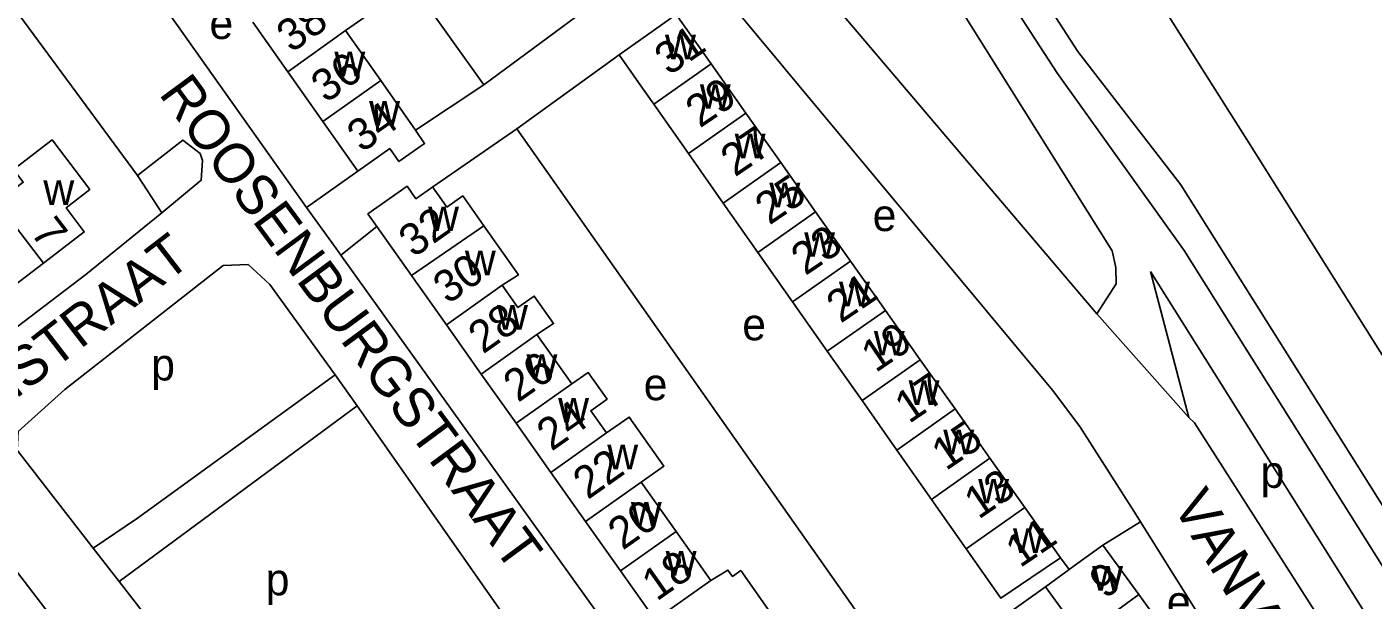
# Model space of a CAD drawing. Extents: x 158848 to 160613, y 385889 to 387762.
# Drawn here: x 160280.6 to 160449.1, y 386672.8 to 386744.6 of the extents above; entities that cross this region are included whole.
import ezdxf

# ---------------------------------------------------------------- set-up
doc = ezdxf.new("R2010")
doc.units = 0
for name, color, linetype in [('BLT_Basislijn', 7, 'Continuous'), ('BLT_Bebouwing', 7, 'Continuous'), ('BLT_Centroide', 7, 'Continuous'), ('BLT_Huisnummer', 7, 'Continuous'), ('BLT_Huisnummer_ tussenligend', 7, 'Continuous'), ('BLT_Onderverdeling_panden', 7, 'Continuous'), ('BLT_Straatnaam', 7, 'Continuous')]:
    doc.layers.add(name, color=color, linetype=linetype)

msp = doc.modelspace()

# ---------------------------------------------------------------- linework, layer by layer
at = {"layer": 'BLT_Basislijn'}
for p, q in [((160373.41, 386825.27), (160433.49, 386730.11)), ((160315.59, 386721.93), (160287.01, 386762.27)), ((160271.82, 386756.68), (160294.41, 386725.95)), ((160337.79, 386737.32), (160349.27, 386745.78)), ((160341.91, 386731.79), (160354.7, 386741.07)), ((160337.79, 386737.32), (160329.23, 386731.61)), ((160341.91, 386731.79), (160331.38, 386724.52)), ((160390.87, 386662.24), (160341.91, 386731.79)), ((160433.49, 386730.11), (160491.73, 386637.45)), ((160297.47, 386721.3), (160294.41, 386725.95)), ((160315.59, 386721.93), (160322.01, 386726.51)), ((160425.02, 386724.79), (160483.26, 386632.13)), ((160324.38, 386719.57), (160319.86, 386716)), ((160426.05, 386695.68), (160414.52, 386708.62)), ((160321.92, 386697.11), (160319.16, 386701)), ((160321.92, 386697.11), (160292.15, 386675.12)), ((160321.92, 386697.11), (160343.06, 386667)), ((160415.28, 386679.69), (160419.96, 386682.62)), ((160419.96, 386682.62), (160433.5, 386661.1)), ((160288.87, 386679.32), (160292.15, 386675.12)), ((160411.06, 386676.64), (160409.96, 386678.1)), ((160314.74, 386645.95), (160292.15, 386675.12)), ((160408.09, 386674.48), (160392.26, 386663.22))]:
    msp.add_line(p, q, dxfattribs=at)
for points in [[(160357.58, 386818.68), (160409.58, 386738.73), (160425.46, 386716.58)], [(160332.3, 386805.38), (160341.21, 386811.28), (160354.98, 386814.58), (160416.45, 386716.52), (160416.9, 386714.44), (160416.93, 386712.38), (160414.52, 386708.62)], [(160332.3, 386805.38), (160414.52, 386708.62)], [(160337.79, 386737.32), (160316.29, 386767.38), (160311.2, 386774.46), (160308.81, 386777.78)], [(160401.65, 386757.71), (160412.15, 386741.49), (160425.02, 386724.79)], [(160419.96, 386682.62), (160419.42, 386683.49), (160412.39, 386694.53), (160408.97, 386699.1), (160367.01, 386749.49)], [(160294.41, 386725.95), (160300.1, 386730.39), (160302.27, 386728.69), (160302.58, 386727.84), (160302.39, 386725.36), (160297.47, 386721.3)], [(160319.86, 386716), (160319.29, 386716.8), (160315.79, 386721.65), (160315.59, 386721.93)], [(160297.47, 386721.3), (160287.96, 386713.58), (160256.88, 386689.9)], [(160425.46, 386716.58), (160511.71, 386579.35), (160518.16, 386566.97)], [(160319.16, 386701), (160310.98, 386712.3), (160308.27, 386714.83), (160305.15, 386714.7), (160285.31, 386699.15), (160279.48, 386693.93), (160279.36, 386691.57), (160288.87, 386679.32)], [(160351.52, 386600.17), (160336.02, 386620.68), (160362.23, 386641.04), (160363.62, 386643.32), (160365.03, 386646.71), (160365.03, 386651.18), (160364.3, 386653.42), (160362.43, 386656.6), (160319.86, 386716)], [(160426.05, 386695.68), (160421.22, 386713.92)], [(160421.22, 386713.92), (160466.78, 386641.44), (160462.63, 386638.83)], [(160319.16, 386701), (160294.41, 386683.05), (160288.87, 386679.32)], [(160462.63, 386638.83), (160426.74, 386694.99), (160426.05, 386695.68)], [(160250.58, 386672.17), (160268.02, 386685.39), (160268.98, 386685.74), (160271.92, 386685.34), (160273.79, 386683.57), (160325.19, 386616.52), (160325.69, 386615.85)]]:
    msp.add_lwpolyline(points, dxfattribs=at)
at = {"layer": 'BLT_Bebouwing'}
for p, q in [((160308.86, 386745.14), (160313.25, 386738.93)), ((160361.86, 386746.09), (160354.7, 386741.07)), ((160366.22, 386739.92), (160361.86, 386746.09)), ((160324.89, 386737.85), (160320.48, 386744.1)), ((160313.25, 386738.93), (160317.63, 386732.72)), ((160370.58, 386733.75), (160366.22, 386739.92)), ((160329.23, 386731.61), (160324.89, 386737.85)), ((160359.05, 386734.88), (160363.39, 386728.7)), ((160374.95, 386727.58), (160370.58, 386733.75)), ((160317.63, 386732.72), (160322.01, 386726.51)), ((160363.39, 386728.7), (160367.74, 386722.51)), ((160379.31, 386721.41), (160374.95, 386727.58)), ((160367.74, 386722.51), (160372.08, 386716.33)), ((160383.68, 386715.24), (160379.31, 386721.41)), ((160324.38, 386719.57), (160328.74, 386713.42)), ((160372.08, 386716.33), (160376.43, 386710.15)), ((160388.04, 386709.07), (160383.68, 386715.24)), ((160328.74, 386713.42), (160333.09, 386707.26)), ((160376.43, 386710.15), (160380.77, 386703.96)), ((160392.41, 386702.9), (160388.04, 386709.07)), ((160333.09, 386707.26), (160337.45, 386701.1)), ((160348.79, 386699.89), (160344.43, 386706.05)), ((160380.77, 386703.96), (160385.12, 386697.78)), ((160396.77, 386696.73), (160392.41, 386702.9)), ((160337.45, 386701.1), (160341.81, 386694.95)), ((160385.12, 386697.78), (160389.46, 386691.59)), ((160401.14, 386690.56), (160396.77, 386696.73)), ((160341.81, 386694.95), (160346.17, 386688.79)), ((160389.46, 386691.59), (160393.81, 386685.41)), ((160405.51, 386684.39), (160401.14, 386690.56)), ((160346.17, 386688.79), (160350.52, 386682.64)), ((160361.85, 386681.41), (160357.49, 386687.57)), ((160393.81, 386685.41), (160398.15, 386679.23)), ((160409.96, 386678.1), (160405.51, 386684.39)), ((160350.52, 386682.64), (160354.88, 386676.48)), ((160366.2, 386675.25), (160361.85, 386681.41)), ((160419.77, 386673.5), (160415.28, 386679.69)), ((160354.88, 386676.48), (160359.24, 386670.32)), ((160408.09, 386674.48), (160411.06, 386676.64)), ((160412.58, 386668.29), (160408.09, 386674.48)), ((160424.26, 386667.31), (160419.77, 386673.5))]:
    msp.add_line(p, q, dxfattribs=at)
for points in [[(160320.48, 386744.1), (160323.03, 386745.89), (160318.63, 386752.03), (160318.05, 386751.62)], [(160354.7, 386741.07), (160357.73, 386736.76), (160359.05, 386734.88)], [(160322.01, 386726.51), (160326, 386729.33), (160327.15, 386727.69), (160330.37, 386729.95), (160329.23, 386731.61)], [(160282.64, 386714.98), (160287.75, 386718.89), (160285.49, 386721.89), (160288.47, 386724.22), (160283.76, 386730.41), (160279.79, 386727.38), (160278.91, 386726.71), (160280.13, 386725.12), (160276.81, 386722.59)], [(160331.38, 386724.52), (160329.28, 386723.04), (160328.17, 386724.61), (160323.27, 386721.15), (160324.38, 386719.57)], [(160337.77, 386719.66), (160335.13, 386723.39), (160333.16, 386722), (160332.19, 386723.38), (160331.53, 386724.3), (160331.38, 386724.52)], [(160276.81, 386722.59), (160273.53, 386720.09), (160272.32, 386721.68), (160267.47, 386717.98), (160269.16, 386715.76), (160272.19, 386711.78), (160275.21, 386714.08), (160277.52, 386711.06), (160282.64, 386714.98)], [(160340.08, 386712.21), (160342.11, 386713.52), (160337.77, 386719.66)], [(160344.43, 386706.05), (160346.52, 386707.43), (160344.1, 386710.87), (160342.05, 386709.42), (160340.08, 386712.21)], [(160353.14, 386693.73), (160351.17, 386696.52), (160353.2, 386697.96), (160350.85, 386701.29), (160348.79, 386699.89)], [(160357.49, 386687.57), (160360.33, 386689.58), (160355.99, 386695.72), (160353.14, 386693.73)], [(160411.06, 386676.64), (160411.86, 386677.21), (160415.28, 386679.69)], [(160398.15, 386679.23), (160402.5, 386673.04), (160406.26, 386675.59), (160409.96, 386678.1)], [(160370.56, 386669.09), (160373.59, 386671.35), (160369.93, 386676.51), (160368.9, 386675.78), (160368.34, 386676.57), (160366.2, 386675.25)]]:
    msp.add_lwpolyline(points, dxfattribs=at)
at = {"layer": 'BLT_Onderverdeling_panden'}
for p, q in [((160313.25, 386738.93), (160320.48, 386744.1)), ((160359.05, 386734.88), (160366.22, 386739.92)), ((160317.63, 386732.72), (160324.89, 386737.85)), ((160363.39, 386728.7), (160370.58, 386733.75)), ((160367.74, 386722.51), (160374.95, 386727.58)), ((160282.64, 386714.98), (160276.81, 386722.59)), ((160372.08, 386716.33), (160379.31, 386721.41)), ((160328.74, 386713.42), (160337.77, 386719.66)), ((160376.43, 386710.15), (160383.68, 386715.24)), ((160333.09, 386707.26), (160340.08, 386712.21)), ((160380.77, 386703.96), (160388.04, 386709.07)), ((160337.45, 386701.1), (160344.43, 386706.05)), ((160385.12, 386697.78), (160392.41, 386702.9)), ((160341.81, 386694.95), (160348.79, 386699.89)), ((160389.46, 386691.59), (160396.77, 386696.73)), ((160346.17, 386688.79), (160353.14, 386693.73)), ((160393.81, 386685.41), (160401.14, 386690.56)), ((160350.52, 386682.64), (160357.49, 386687.57)), ((160398.15, 386679.23), (160405.51, 386684.39)), ((160354.88, 386676.48), (160361.85, 386681.41)), ((160359.24, 386670.32), (160366.2, 386675.25)), ((160412.58, 386668.29), (160419.77, 386673.5))]:
    msp.add_line(p, q, dxfattribs=at)

# ---------------------------------------------------------------- texts
at = {"layer": 'BLT_Centroide'}
for s, p in [('e', (160303.43, 386743.04)), ('w', (160360.46, 386740.5)), ('w', (160319.07, 386738.38)), ('w', (160364.82, 386734.31)), ('w', (160323.42, 386732.19)), ('w', (160369.18, 386728.12)), ('w', (160282.64, 386722.27)), ('w', (160373.52, 386721.97)), ('w', (160330.8, 386719)), ('e', (160386.45, 386719)), ('w', (160377.88, 386715.78)), ('w', (160335.41, 386713.47)), ('w', (160382.24, 386709.59)), ('w', (160339.43, 386706.66)), ('e', (160370.13, 386705.33)), ('w', (160386.6, 386703.44)), ('p', (160296.14, 386700.3)), ('w', (160343.12, 386700.5)), ('e', (160357.79, 386697.83)), ('w', (160390.95, 386697.25)), ('w', (160347.08, 386695.03)), ('w', (160395.3, 386691.06)), ('w', (160353.23, 386689.19)), ('p', (160435.01, 386686.86)), ('w', (160399.66, 386684.91)), ('w', (160356.18, 386682.03)), ('w', (160404.02, 386678.72)), ('w', (160360.54, 386675.88)), ('p', (160310.47, 386673.41)), ('w', (160413.93, 386674)), ('e', (160423.28, 386670.6))]:
    msp.add_text(s, height=4, dxfattribs=at).set_placement(p)
at = {"layer": 'BLT_Huisnummer'}
for s, rotation, p in [('38', 35.2201, (160313.69, 386741.23)), ('31', 34.135, (160360.94, 386738.38)), ('34', 35.2148, (160322.51, 386728.73)), ('27', 34.135, (160369.21, 386725.7)), ('32', 35.1679, (160328.98, 386715.59)), ('7', 307.409, (160280.93, 386718.78)), ('23', 34.135, (160378.02, 386713.35)), ('28', 35.1679, (160337.68, 386703.54)), ('19', 34.135, (160386.81, 386701.19)), ('24', 35.1679, (160346.25, 386691.36)), ('15', 34.135, (160395.62, 386688.93)), ('20', 35.1679, (160355.16, 386678.98)), ('11', 34.135, (160404.89, 386676.77)), ('9', 35.9501, (160415.51, 386672.86))]:
    msp.add_text(s, height=4, rotation=rotation, dxfattribs=at).set_placement(p)
at = {"layer": 'BLT_Huisnummer_ tussenligend'}
for s, rotation, p in [('36', 35.2148, (160318.01, 386734.94)), ('29', 34.135, (160364.82, 386731.82)), ('25', 34.135, (160373.52, 386719.67)), ('30', 35.1679, (160333.28, 386709.76)), ('21', 34.135, (160382.45, 386707.39)), ('26', 35.1679, (160342.07, 386697.47)), ('17', 34.135, (160391, 386694.82)), ('22', 35.1679, (160350.79, 386685.31)), ('13', 34.135, (160399.7, 386682.84)), ('18', 35.1679, (160359.42, 386672.59))]:
    msp.add_text(s, height=4, rotation=rotation, dxfattribs=at).set_placement(p)
at = {"layer": 'BLT_Straatnaam'}
for s, height, rotation, p in [('ROOSENBURGSTRAAT', 4.9999, 306.4127, (160297, 386736.17)), ('VAN HEUKELOMSTRAAT', 5, 37.6482, (160238.42, 386666.49)), ('VANVITELLIWEG', 5, 301.013, (160423.9, 386684.7))]:
    msp.add_text(s, height=height, rotation=rotation, dxfattribs=at).set_placement(p)

doc.saveas('drawing.dxf')
